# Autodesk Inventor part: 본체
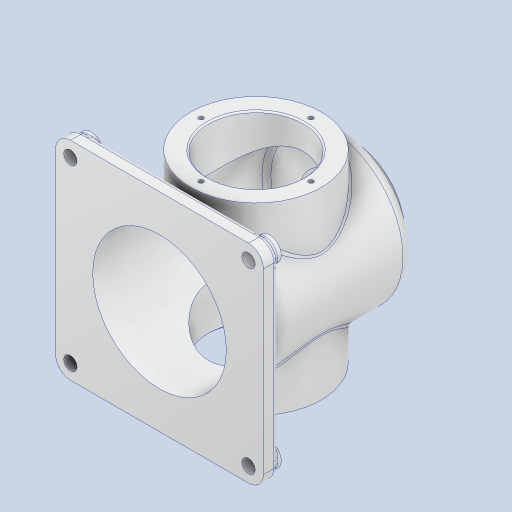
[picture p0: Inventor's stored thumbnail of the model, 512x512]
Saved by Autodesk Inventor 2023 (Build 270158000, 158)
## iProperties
Created: 2025-05
Part Number: 본체
Material: 알루미늄 6061
Document SubType Name: Modeling
Designer: Admin
Density: 2.7 g/cm^3
Appearance: 알루미늄 - 평지
Mass: 1130.88 g
Surface Area: 1201.4 cm^2
Volume: 418.845 cm^3
Author: Admin
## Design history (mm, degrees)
sketch "스케치1"
  geometry: L1 (-70, 0)-(70, 0) reference; L2 (0, -70)-(0, 70) reference; C1 r 50 at (0, 0); 1 further point
  constraints: 1 centre point, 1 coincident
  dimensions: "d0" = 100 diameter of C1
extrude "돌출1" new body sketch "스케치1" distance "d1" = 55; taper "d3" = 0 deg; dims "d2" = 57, "d4" = 0
sketch "스케치2"
  geometry: L1 (-70, -70)-(70, -70); L2 (70, -70)-(70, 70); L3 (70, 70)-(-70, 70); L4 (-70, 70)-(-70, -70); L5 (-70, -70)-(70, 70); L6 (70, -70)-(-70, 70); 1 further point
  constraints: 12 end point, 2 midpoint, 2 parallel, 1 horizontal, 1 perpendicular
  dimensions: "d5" = 140 distance of L2.end L3.end; "d6" = 140 distance of L1.end L2.end
extrude "돌출2" join sketch "스케치2" distance "d7" = 10; taper "d8" = 0 deg
sketch "스케치3"
  geometry: L1 (98, 0)-(-98, 0) reference; L2 (0, -98)-(0, 98) reference; C1 r 35 at (0, 0); 1 further point
  constraints: 1 centre point, 1 coincident
  dimensions: "d9" = 70 diameter of C1
extrude "돌출3" join sketch "스케치3" distance "d10" = 8; taper "d11" = 0 deg
sketch "스케치4"
  geometry: L1 (98, 0)-(-98, 0) reference; L2 (0, -91)-(0, 91) reference; C1 r 44 at (0, 0); 1 further point
  constraints: 1 centre point, 1 coincident
  dimensions: "d12" = 88 diameter of C1
extrude "돌출4" join sketch "스케치4" stored distance "d13" = 124; taper "d14" = 0 deg
sketch "스케치5"
  geometry: L1 (0, 91)-(0, -91) reference; L2 (-98, 0)-(98, 0) reference; C1 r 32 at (0, 0); 1 further point
  constraints: 1 centre point, 1 coincident
  dimensions: "d15" = 64 diameter of C1
extrude "돌출5" cut sketch "스케치5" distance "d16" = 124; taper "d17" = 0 deg
sketch "스케치6"
  geometry: L1 (98, 0)-(-98, 0) reference; L2 (0, -98)-(0, 98) reference; C1 r 23 at (0, 0); 1 further point
  constraints: 1 centre point, 1 coincident
  dimensions: "d18" = 46 diameter of C1
extrude "돌출6" cut sketch "스케치6" stored distance "d19" = 124; taper "d20" = 0 deg
sketch "스케치7"
  geometry: L1 (-98, 0)-(98, 0) reference; L2 (0, -98)-(0, 98) reference; C1 r 45 at (0, 0); 1 further point
  constraints: 1 centre point, 1 coincident
  dimensions: "d21" = 90 diameter of C1
extrude "돌출7" cut sketch "스케치7" distance "d22" = 117; taper "d23" = 0 deg
fillet "모깎기1" dims "d24" = 10
sketch "스케치8"
  geometry: L1 (98, 0)-(-98, 0) reference; L2 (0, -98)-(0, 98) reference; C1 r 8 at (60, -60); C2 r 8 at (-60, -60); C3 r 8 at (60, 60); C4 r 8 at (-60, 60); A1 r 10 centre (60, -60) between (60, -70) and (70, -60) reference; 1 further point
  constraints: 4 centre point, 3 symmetric about line, 1 coincident, 3 other
  dimensions: "d26" = 16 diameter of C1
extrude "돌출8" join sketch "스케치8" distance "d27" = 4; taper "d28" = 0 deg
fillet "모깎기2" dims "d29" = 3
fillet "모깎기3" dims "d30" = 3
chamfer "모따기1" distance "d31" = 1; stored, may be unused: second distance "d32" = 2, angle "d33" = 45 deg
fillet "모깎기4" dims "d34" = 3
fillet "모깎기5" dims "d35" = 8
sketch "스케치9"
  geometry: L1 (-98, 0)-(98, 0) reference; L2 (0, 91)-(0, -91) reference; 2 further points
  constraints: 1 point on line
  dimensions: "d36" = 74 diameter of point (0, 37) L1
hole "구멍1" sketch "스케치9" at (0, 37) diameter "d37" = 3.242; stored, may be unused: countersink angle "d41" = 90 deg, drill point angle "d43" = 118 deg; dims "d38" = 8, "d39" = 4, "d40" = 2, "d42" = 10
sketch "스케치10"
  geometry: L1 (98, 0)-(-98, 0) reference; L2 (0, -98)-(0, 98) reference; 2 further points
  constraints: 1 point on line
  dimensions: "d47" = 56 diameter of point (28, 0) L2
hole "구멍2" sketch "스케치10" at (28, 0) diameter "d48" = 3.242; stored, may be unused: countersink angle "d52" = 90 deg, drill point angle "d54" = 118 deg; dims "d49" = 8, "d50" = 4, "d51" = 2, "d53" = 10
sketch "스케치11"
  geometry: L1 (158.414, -60)-(-40.485, -60) reference; L2 (60, -158.414)-(60, 40.485) reference; C1 r 4.5 at (0, 0); C2 r 4.5 at (0, -120); C3 r 4.5 at (120, 0); C4 r 4.5 at (120, -120); A1 r 10 centre (0, 0) between (0, 10) and (-10, 0) reference; 1 further point
  constraints: 4 centre point, 3 symmetric about line, 1 coincident, 3 other
  dimensions: "d58" = 9 diameter of C1
extrude "돌출9" cut sketch "스케치11" stored distance "d59" = 4; taper "d60" = 0 deg
node "작업 평면1"
sketch "스케치12"
  geometry: L1 (0, -91)-(0, 91) reference; L2 (-60, 65)-(60, 65) reference; 2 further points
  constraints: 1 point on line, 1 other
  dimensions: "d62" = 80 distance from line of L2 point (0, -15)
feature "엠보싱1" sketch "스케치12" dims "d63" = 0.5, "d64" = 0
node "솔리드1"
pattern_circular "원형 패턴1" dims angle "d45" = 360 deg
mirror "미러1"
pattern_circular "원형 패턴2" dims angle "d56" = 360 deg
feature "A9D066F2-1C7D-4E18-AEED-F7BC21143FA4" dims "d37" = 3.242, "d38" = 8, "d39" = 4, "d40" = 2, "d41" = 90 deg, "d42" = 10, "d43" = 118 deg
other parameters: "d61" = -100.0125
